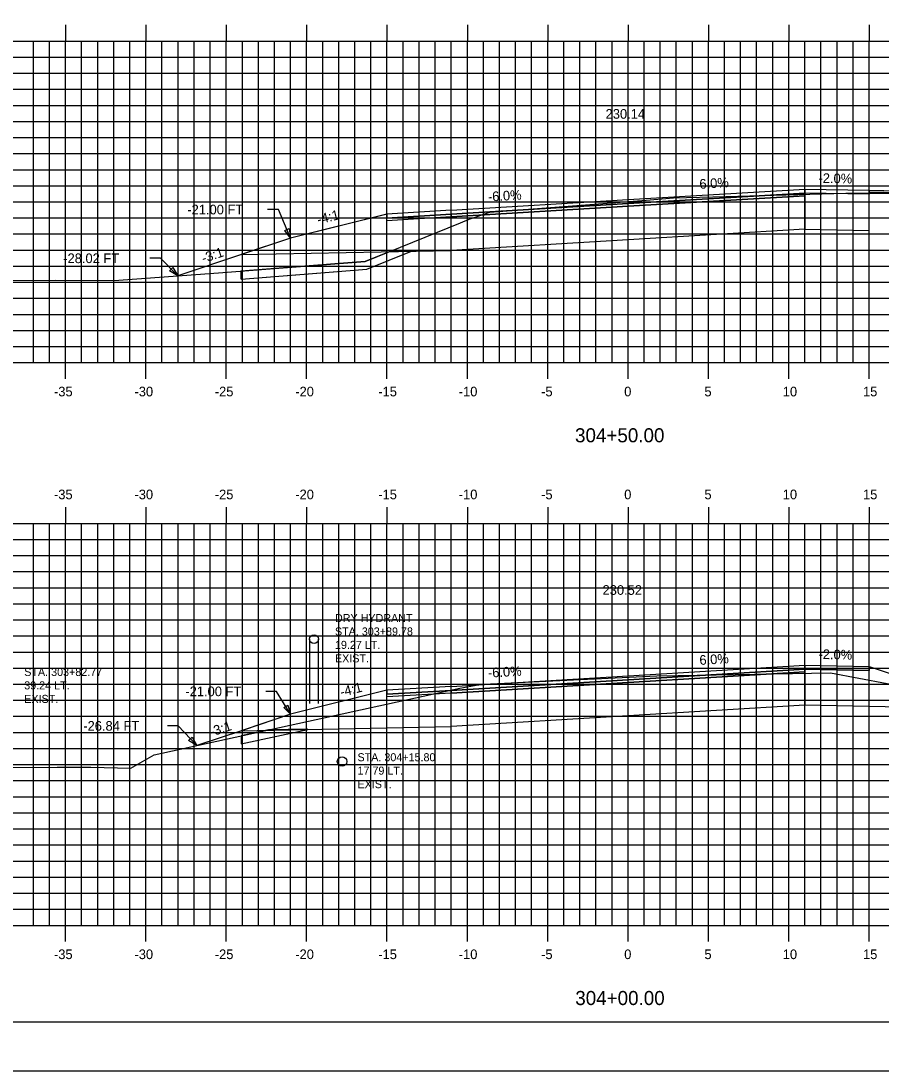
# Model space of a CAD drawing. Extents: x 1136989 to 1137159, y 608981 to 609091.
# Drawn here: x 1137034.4 to 1137087.9, y 608981.3 to 609046.6 of the extents above; entities that cross this region are included whole.
import ezdxf

# ---------------------------------------------------------------- set-up
doc = ezdxf.new("R2010")
doc.units = 0
for name, color, linetype in [('ANNOTATION', 7, 'Continuous'), ('BORDER', 7, 'Continuous'), ('D_Roadway_Centerline', 7, 'Continuous'), ('D_Roadway_Centerline_Text', 7, 'Continuous'), ('D_Roadway_Edge_Shoulder', 7, 'Continuous'), ('D_Roadway_Edge_TW', 7, 'Continuous'), ('D_Roadway_Pavement', 7, 'Continuous'), ('D_Roadway_SlopeLines', 7, 'Continuous'), ('D_Roadway_SubGrade', 7, 'Continuous'), ('D_Text_Monospaced', 7, 'Continuous'), ('D_Text_Standard', 7, 'Continuous'), ('H_V ANNOTATION', 7, 'Continuous'), ('MAJOR', 7, 'Continuous'), ('MINOR', 7, 'Continuous'), ('PLOT BOUNDARY', 7, 'Continuous'), ('S_Drainage_Invert', 7, 'Continuous'), ('S_Roadway_Centerline', 7, 'Continuous'), ('S_Traffic_Post_Conc', 7, 'Continuous'), ('SHADING', 7, 'Continuous')]:
    doc.layers.add(name, color=color, linetype=linetype)

msp = doc.modelspace()

# ---------------------------------------------------------------- linework, layer by layer
at = {"layer": 'BORDER'}
msp.add_lwpolyline([(1136997.14, 608984.335), (1137157.14, 608984.335), (1137157.14, 609089.335), (1136997.14, 609089.335)], close=True, dxfattribs=at)
at = {"layer": 'D_Roadway_Centerline'}
for points in [[(1137057.141, 609034.572), (1137051.141, 609033.073), (1137048.141, 609032.073), (1137044.117, 609030.731)], [(1137057.14, 609004.96), (1137051.14, 609003.46), (1137048.14, 609002.46), (1137045.302, 609001.514)]]:
    msp.add_lwpolyline(points, dxfattribs=at)
at = {"layer": 'D_Roadway_Edge_Shoulder'}
for points in [[(1137083.14, 609036.132), (1137087.14, 609036.052), (1137087.14, 609035.802), (1137083.14, 609035.882)], [(1137061.14, 609034.812), (1137057.14, 609034.572), (1137057.14, 609034.322), (1137061.14, 609034.562)], [(1137083.14, 609006.52), (1137087.14, 609006.44), (1137087.14, 609006.19), (1137083.14, 609006.27)], [(1137061.14, 609005.2), (1137057.14, 609004.96), (1137057.14, 609004.71), (1137061.14, 609004.95)]]:
    msp.add_lwpolyline(points, close=True, dxfattribs=at)
msp.add_lwpolyline([(1137087.14, 609036.052), (1137091.698, 609035.961), (1137091.695, 609035.836), (1137087.14, 609035.927)], dxfattribs=at)
at = {"layer": 'D_Roadway_Edge_TW'}
for points in [[(1137061.14, 609034.562), (1137061.14, 609034.812), (1137072.14, 609035.472), (1137083.14, 609036.132), (1137083.14, 609035.882), (1137072.14, 609035.222)], [(1137061.14, 609034.396), (1137057.14, 609034.158), (1137057.14, 609034.322), (1137061.14, 609034.562)], [(1137061.14, 609004.95), (1137061.14, 609005.2), (1137072.14, 609005.86), (1137083.14, 609006.52), (1137083.14, 609006.27), (1137072.14, 609005.61)], [(1137061.14, 609004.783), (1137057.14, 609004.543), (1137057.14, 609004.71), (1137061.14, 609004.95)]]:
    msp.add_lwpolyline(points, close=True, dxfattribs=at)
at = {"layer": 'D_Roadway_Pavement'}
for points in [[(1137061.14, 609034.396), (1137061.14, 609034.562), (1137072.14, 609035.222), (1137083.14, 609035.882), (1137083.14, 609035.716), (1137072.14, 609035.056)], [(1137061.14, 609004.783), (1137061.14, 609004.95), (1137072.14, 609005.61), (1137083.14, 609006.27), (1137083.14, 609006.103), (1137072.14, 609005.443)]]:
    msp.add_lwpolyline(points, close=True, dxfattribs=at)
at = {"layer": 'D_Roadway_SlopeLines'}
msp.add_line((1137048.076, 609030.525), (1137048.076, 609031.025), dxfattribs=at)
for points in [[(1137048.076, 609030.525), (1137055.894, 609031.14), (1137058.668, 609032.263)], [(1137048.075, 609002.119), (1137048.075, 609001.619), (1137052.206, 609002.521)]]:
    msp.add_lwpolyline(points, dxfattribs=at)
at = {"layer": 'D_Roadway_SubGrade'}
for points in [[(1137061.14, 609032.312), (1137061.14, 609034.396), (1137072.14, 609035.056), (1137083.14, 609035.716), (1137083.14, 609033.632), (1137072.14, 609032.972)], [(1137087.14, 609035.052), (1137087.14, 609036.052), (1137087.14, 609036.052), (1137087.14, 609035.802), (1137083.14, 609035.882), (1137083.14, 609035.716), (1137083.14, 609033.632), (1137087.14, 609033.552)], [(1137061.14, 609034.396), (1137061.14, 609034.562), (1137057.14, 609034.322), (1137057.14, 609034.572), (1137057.139, 609034.572), (1137051.141, 609033.073), (1137048.076, 609032.051), (1137061.14, 609032.312)], [(1137083.14, 609006.103), (1137083.14, 609006.27), (1137087.14, 609006.19), (1137087.14, 609006.44), (1137087.14, 609006.44), (1137095.119, 609003.78), (1137083.14, 609004.02)], [(1137061.14, 609002.7), (1137061.14, 609004.783), (1137072.14, 609005.443), (1137083.14, 609006.103), (1137083.14, 609004.02), (1137072.14, 609003.36)], [(1137061.14, 609004.783), (1137061.14, 609004.95), (1137057.14, 609004.71), (1137057.14, 609004.96), (1137057.139, 609004.96), (1137051.14, 609003.46), (1137048.075, 609002.438), (1137061.14, 609002.7)]]:
    msp.add_lwpolyline(points, close=True, dxfattribs=at)
at = {"layer": 'D_Text_Standard'}
for points in [[(1137051.141, 609033.073), (1137050.392, 609034.854), (1137049.712, 609034.854)], [(1137044.117, 609030.731), (1137043.057, 609031.823), (1137042.377, 609031.823)], [(1137051.14, 609003.46), (1137050.271, 609004.887), (1137049.591, 609004.887)], [(1137045.302, 609001.514), (1137044.154, 609002.742), (1137043.474, 609002.742)]]:
    msp.add_lwpolyline(points, dxfattribs=at)
for points in [[(1137051.141, 609033.073), (1137050.781, 609033.553), (1137051.049, 609033.666)], [(1137044.117, 609030.731), (1137043.607, 609031.048), (1137043.816, 609031.25)], [(1137051.14, 609003.46), (1137050.713, 609003.881), (1137050.961, 609004.033)], [(1137045.302, 609001.514), (1137044.799, 609001.84), (1137045.011, 609002.039)]]:
    msp.add_lwpolyline(points, close=True, dxfattribs=at)
at = {"layer": 'MAJOR'}
for p, q in [((1137037.14, 609046.337), (1137037.14, 609045.335)), ((1137042.14, 609046.337), (1137042.14, 609045.335)), ((1137047.14, 609046.337), (1137047.14, 609045.335)), ((1137052.14, 609046.337), (1137052.14, 609045.335)), ((1137057.14, 609046.337), (1137057.14, 609045.335)), ((1137062.14, 609046.337), (1137062.14, 609045.335)), ((1137067.14, 609046.337), (1137067.14, 609045.335)), ((1137072.14, 609046.337), (1137072.14, 609045.335)), ((1137077.14, 609046.337), (1137077.14, 609045.335)), ((1137082.14, 609046.337), (1137082.14, 609045.335)), ((1137087.14, 609046.337), (1137087.14, 609045.335)), ((1137002.14, 609045.335), (1137142.14, 609045.335)), ((1137002.14, 609045.335), (1137142.14, 609045.335)), ((1137037.14, 609025.335), (1137037.14, 609045.335)), ((1137042.14, 609025.335), (1137042.14, 609045.335)), ((1137047.14, 609025.335), (1137047.14, 609045.335)), ((1137052.14, 609025.335), (1137052.14, 609045.335)), ((1137057.14, 609025.335), (1137057.14, 609045.335)), ((1137062.14, 609025.335), (1137062.14, 609045.335)), ((1137067.14, 609025.335), (1137067.14, 609045.335)), ((1137072.14, 609025.335), (1137072.14, 609045.335)), ((1137077.14, 609025.335), (1137077.14, 609045.335)), ((1137082.14, 609025.335), (1137082.14, 609045.335)), ((1137087.14, 609025.335), (1137087.14, 609045.335)), ((1137002.14, 609040.335), (1137142.14, 609040.335)), ((1137002.14, 609035.335), (1137142.14, 609035.335)), ((1137002.14, 609030.335), (1137142.14, 609030.335)), ((1137002.14, 609025.335), (1137142.14, 609025.335)), ((1137002.14, 609025.335), (1137142.14, 609025.335)), ((1137037.14, 609024.333), (1137037.14, 609025.335)), ((1137042.14, 609024.333), (1137042.14, 609025.335)), ((1137047.14, 609024.333), (1137047.14, 609025.335)), ((1137052.14, 609024.333), (1137052.14, 609025.335)), ((1137057.14, 609024.333), (1137057.14, 609025.335)), ((1137062.14, 609024.333), (1137062.14, 609025.335)), ((1137067.14, 609024.333), (1137067.14, 609025.335)), ((1137072.14, 609024.333), (1137072.14, 609025.335)), ((1137077.14, 609024.333), (1137077.14, 609025.335)), ((1137082.14, 609024.333), (1137082.14, 609025.335)), ((1137087.14, 609024.333), (1137087.14, 609025.335)), ((1137037.14, 609016.337), (1137037.14, 609015.335)), ((1137042.14, 609016.337), (1137042.14, 609015.335)), ((1137047.14, 609016.337), (1137047.14, 609015.335)), ((1137052.14, 609016.337), (1137052.14, 609015.335)), ((1137057.14, 609016.337), (1137057.14, 609015.335)), ((1137062.14, 609016.337), (1137062.14, 609015.335)), ((1137067.14, 609016.337), (1137067.14, 609015.335)), ((1137072.14, 609016.337), (1137072.14, 609015.335)), ((1137077.14, 609016.337), (1137077.14, 609015.335)), ((1137082.14, 609016.337), (1137082.14, 609015.335)), ((1137087.14, 609016.337), (1137087.14, 609015.335)), ((1137002.14, 609015.335), (1137142.14, 609015.335)), ((1137002.14, 609015.335), (1137142.14, 609015.335)), ((1137037.14, 608990.335), (1137037.14, 609015.335)), ((1137042.14, 608990.335), (1137042.14, 609015.335)), ((1137047.14, 608990.335), (1137047.14, 609015.335)), ((1137052.14, 608990.335), (1137052.14, 609015.335)), ((1137057.14, 608990.335), (1137057.14, 609015.335)), ((1137062.14, 608990.335), (1137062.14, 609015.335)), ((1137067.14, 608990.335), (1137067.14, 609015.335)), ((1137072.14, 608990.335), (1137072.14, 609015.335)), ((1137077.14, 608990.335), (1137077.14, 609015.335)), ((1137082.14, 608990.335), (1137082.14, 609015.335)), ((1137087.14, 608990.335), (1137087.14, 609015.335)), ((1137002.14, 609010.335), (1137142.14, 609010.335)), ((1137002.14, 609005.335), (1137142.14, 609005.335)), ((1137002.14, 609000.335), (1137142.14, 609000.335)), ((1137002.14, 608995.335), (1137142.14, 608995.335)), ((1137002.14, 608990.335), (1137142.14, 608990.335)), ((1137002.14, 608990.335), (1137142.14, 608990.335)), ((1137037.14, 608989.333), (1137037.14, 608990.335)), ((1137042.14, 608989.333), (1137042.14, 608990.335)), ((1137047.14, 608989.333), (1137047.14, 608990.335)), ((1137052.14, 608989.333), (1137052.14, 608990.335)), ((1137057.14, 608989.333), (1137057.14, 608990.335)), ((1137062.14, 608989.333), (1137062.14, 608990.335)), ((1137067.14, 608989.333), (1137067.14, 608990.335)), ((1137072.14, 608989.333), (1137072.14, 608990.335)), ((1137077.14, 608989.333), (1137077.14, 608990.335)), ((1137082.14, 608989.333), (1137082.14, 608990.335)), ((1137087.14, 608989.333), (1137087.14, 608990.335))]:
    msp.add_line(p, q, dxfattribs=at)
at = {"layer": 'MINOR'}
for p, q in [((1137035.14, 609025.335), (1137035.14, 609045.335)), ((1137036.14, 609025.335), (1137036.14, 609045.335)), ((1137038.14, 609025.335), (1137038.14, 609045.335)), ((1137039.14, 609025.335), (1137039.14, 609045.335)), ((1137040.14, 609025.335), (1137040.14, 609045.335)), ((1137041.14, 609025.335), (1137041.14, 609045.335)), ((1137043.14, 609025.335), (1137043.14, 609045.335)), ((1137044.14, 609025.335), (1137044.14, 609045.335)), ((1137045.14, 609025.335), (1137045.14, 609045.335)), ((1137046.14, 609025.335), (1137046.14, 609045.335)), ((1137048.14, 609025.335), (1137048.14, 609045.335)), ((1137049.14, 609025.335), (1137049.14, 609045.335)), ((1137050.14, 609025.335), (1137050.14, 609045.335)), ((1137051.14, 609025.335), (1137051.14, 609045.335)), ((1137053.14, 609025.335), (1137053.14, 609045.335)), ((1137054.14, 609025.335), (1137054.14, 609045.335)), ((1137055.14, 609025.335), (1137055.14, 609045.335)), ((1137056.14, 609025.335), (1137056.14, 609045.335)), ((1137058.14, 609025.335), (1137058.14, 609045.335)), ((1137059.14, 609025.335), (1137059.14, 609045.335)), ((1137060.14, 609025.335), (1137060.14, 609045.335)), ((1137061.14, 609025.335), (1137061.14, 609045.335)), ((1137063.14, 609025.335), (1137063.14, 609045.335)), ((1137064.14, 609025.335), (1137064.14, 609045.335)), ((1137065.14, 609025.335), (1137065.14, 609045.335)), ((1137066.14, 609025.335), (1137066.14, 609045.335)), ((1137068.14, 609025.335), (1137068.14, 609045.335)), ((1137069.14, 609025.335), (1137069.14, 609045.335)), ((1137070.14, 609025.335), (1137070.14, 609045.335)), ((1137071.14, 609025.335), (1137071.14, 609045.335)), ((1137073.14, 609025.335), (1137073.14, 609045.335)), ((1137074.14, 609025.335), (1137074.14, 609045.335)), ((1137075.14, 609025.335), (1137075.14, 609045.335)), ((1137076.14, 609025.335), (1137076.14, 609045.335)), ((1137078.14, 609025.335), (1137078.14, 609045.335)), ((1137079.14, 609025.335), (1137079.14, 609045.335)), ((1137080.14, 609025.335), (1137080.14, 609045.335)), ((1137081.14, 609025.335), (1137081.14, 609045.335)), ((1137083.14, 609025.335), (1137083.14, 609045.335)), ((1137084.14, 609025.335), (1137084.14, 609045.335)), ((1137085.14, 609025.335), (1137085.14, 609045.335)), ((1137086.14, 609025.335), (1137086.14, 609045.335)), ((1137002.14, 609044.335), (1137142.14, 609044.335)), ((1137002.14, 609043.335), (1137142.14, 609043.335)), ((1137002.14, 609042.335), (1137142.14, 609042.335)), ((1137002.14, 609041.335), (1137142.14, 609041.335)), ((1137002.14, 609039.335), (1137142.14, 609039.335)), ((1137002.14, 609038.335), (1137142.14, 609038.335)), ((1137002.14, 609037.335), (1137142.14, 609037.335)), ((1137002.14, 609036.335), (1137142.14, 609036.335)), ((1137002.14, 609034.335), (1137142.14, 609034.335)), ((1137002.14, 609033.335), (1137142.14, 609033.335)), ((1137002.14, 609032.335), (1137142.14, 609032.335)), ((1137002.14, 609031.335), (1137142.14, 609031.335)), ((1137002.14, 609029.335), (1137142.14, 609029.335)), ((1137002.14, 609028.335), (1137142.14, 609028.335)), ((1137002.14, 609027.335), (1137142.14, 609027.335)), ((1137002.14, 609026.335), (1137142.14, 609026.335)), ((1137035.14, 608990.335), (1137035.14, 609015.335)), ((1137036.14, 608990.335), (1137036.14, 609015.335)), ((1137038.14, 608990.335), (1137038.14, 609015.335)), ((1137039.14, 608990.335), (1137039.14, 609015.335)), ((1137040.14, 608990.335), (1137040.14, 609015.335)), ((1137041.14, 608990.335), (1137041.14, 609015.335)), ((1137043.14, 608990.335), (1137043.14, 609015.335)), ((1137044.14, 608990.335), (1137044.14, 609015.335)), ((1137045.14, 608990.335), (1137045.14, 609015.335)), ((1137046.14, 608990.335), (1137046.14, 609015.335)), ((1137048.14, 608990.335), (1137048.14, 609015.335)), ((1137049.14, 608990.335), (1137049.14, 609015.335)), ((1137050.14, 608990.335), (1137050.14, 609015.335)), ((1137051.14, 608990.335), (1137051.14, 609015.335)), ((1137053.14, 608990.335), (1137053.14, 609015.335)), ((1137054.14, 608990.335), (1137054.14, 609015.335)), ((1137055.14, 608990.335), (1137055.14, 609015.335)), ((1137056.14, 608990.335), (1137056.14, 609015.335)), ((1137058.14, 608990.335), (1137058.14, 609015.335)), ((1137059.14, 608990.335), (1137059.14, 609015.335)), ((1137060.14, 608990.335), (1137060.14, 609015.335)), ((1137061.14, 608990.335), (1137061.14, 609015.335)), ((1137063.14, 608990.335), (1137063.14, 609015.335)), ((1137064.14, 608990.335), (1137064.14, 609015.335)), ((1137065.14, 608990.335), (1137065.14, 609015.335)), ((1137066.14, 608990.335), (1137066.14, 609015.335)), ((1137068.14, 608990.335), (1137068.14, 609015.335)), ((1137069.14, 608990.335), (1137069.14, 609015.335)), ((1137070.14, 608990.335), (1137070.14, 609015.335)), ((1137071.14, 608990.335), (1137071.14, 609015.335)), ((1137073.14, 608990.335), (1137073.14, 609015.335)), ((1137074.14, 608990.335), (1137074.14, 609015.335)), ((1137075.14, 608990.335), (1137075.14, 609015.335)), ((1137076.14, 608990.335), (1137076.14, 609015.335)), ((1137078.14, 608990.335), (1137078.14, 609015.335)), ((1137079.14, 608990.335), (1137079.14, 609015.335)), ((1137080.14, 608990.335), (1137080.14, 609015.335)), ((1137081.14, 608990.335), (1137081.14, 609015.335)), ((1137083.14, 608990.335), (1137083.14, 609015.335)), ((1137084.14, 608990.335), (1137084.14, 609015.335)), ((1137085.14, 608990.335), (1137085.14, 609015.335)), ((1137086.14, 608990.335), (1137086.14, 609015.335)), ((1137002.14, 609014.335), (1137142.14, 609014.335)), ((1137002.14, 609013.335), (1137142.14, 609013.335)), ((1137002.14, 609012.335), (1137142.14, 609012.335)), ((1137002.14, 609011.335), (1137142.14, 609011.335)), ((1137002.14, 609009.335), (1137142.14, 609009.335)), ((1137002.14, 609008.335), (1137142.14, 609008.335)), ((1137002.14, 609007.335), (1137142.14, 609007.335)), ((1137002.14, 609006.335), (1137142.14, 609006.335)), ((1137002.14, 609004.335), (1137142.14, 609004.335)), ((1137002.14, 609003.335), (1137142.14, 609003.335)), ((1137002.14, 609002.335), (1137142.14, 609002.335)), ((1137002.14, 609001.335), (1137142.14, 609001.335)), ((1137002.14, 608999.335), (1137142.14, 608999.335)), ((1137002.14, 608998.335), (1137142.14, 608998.335)), ((1137002.14, 608997.335), (1137142.14, 608997.335)), ((1137002.14, 608996.335), (1137142.14, 608996.335)), ((1137002.14, 608994.335), (1137142.14, 608994.335)), ((1137002.14, 608993.335), (1137142.14, 608993.335)), ((1137002.14, 608992.335), (1137142.14, 608992.335)), ((1137002.14, 608991.335), (1137142.14, 608991.335))]:
    msp.add_line(p, q, dxfattribs=at)
at = {"layer": 'PLOT BOUNDARY'}
msp.add_lwpolyline([(1136989.047, 608981.276), (1137159.047, 608981.276), (1137159.047, 609091.276), (1136989.047, 609091.276)], close=True, dxfattribs=at)
at = {"layer": 'S_Drainage_Invert'}
msp.add_circle((1137054.348, 609000.526), 0.3, dxfattribs=at)
at = {"layer": 'S_Roadway_Centerline'}
for points in [[(1137002.14, 609030.462), (1137003.399, 609030.449), (1137006.342, 609030.492), (1137015.185, 609030.419), (1137018.549, 609030.394), (1137019.238, 609030.446), (1137022.99, 609030.389), (1137036.519, 609030.456), (1137040.174, 609030.448), (1137046.657, 609030.914), (1137055.778, 609031.631), (1137061.718, 609034.034), (1137062.247, 609034.265), (1137063.541, 609034.695), (1137073.261, 609035.448), (1137074.968, 609035.579), (1137078.218, 609035.668), (1137085.691, 609035.878), (1137089.945, 609035.87)], [(1137002.14, 609000.098), (1137009.532, 609000.178), (1137012.739, 609000.098), (1137016.466, 609000.152), (1137036.626, 609000.169), (1137038.714, 609000.163), (1137041.2, 609000.115), (1137042.648, 609000.935), (1137061.665, 609005.086), (1137063.035, 609005.338), (1137063.585, 609005.359), (1137073.925, 609005.86), (1137075.247, 609005.88), (1137084.732, 609006.033), (1137090.016, 609005.053), (1137090.597, 609004.926), (1137092.675, 609004.125), (1137094.237, 609003.522), (1137106.232, 609002.947), (1137113.452, 609002.818), (1137121.89, 609002.73), (1137136.879, 609002.44), (1137141.584, 609002.392), (1137142.14, 609002.4)]]:
    msp.add_lwpolyline(points, dxfattribs=at)
at = {"layer": 'S_Traffic_Post_Conc'}
for p, q in [((1137052.329, 609004.134), (1137052.329, 609008.134)), ((1137052.87, 609004.134), (1137052.87, 609008.134))]:
    msp.add_line(p, q, dxfattribs=at)
msp.add_circle((1137052.599, 609008.134), 0.271, dxfattribs=at)
at = {"layer": 'SHADING'}
for p, q in [((1137049.774, 609002.49), (1137048.075, 609002.119)), ((1137052.206, 609002.535), (1137049.774, 609002.49))]:
    msp.add_line(p, q, dxfattribs=at)
msp.add_lwpolyline([(1137048.076, 609031.025), (1137048.076, 609030.525), (1137051.985, 609030.833), (1137055.894, 609031.14), (1137058.668, 609032.263), (1137057.27, 609032.235), (1137055.778, 609031.631), (1137051.218, 609031.272)], close=True, dxfattribs=at)
for points in [[(1137048.075, 609002.119), (1137048.075, 609001.619), (1137052.206, 609002.521)], [(1137052.206, 609002.521), (1137052.206, 609002.535)]]:
    msp.add_lwpolyline(points, dxfattribs=at)

# ---------------------------------------------------------------- texts
at = {"layer": 'ANNOTATION'}
for s, rotation, p in [('6.0%', 3.43363, (1137076.597, 609036.142)), ('-2.0%', 358.85424, (1137083.983, 609036.516)), ('-6.0%', 3.43363, (1137063.437, 609035.352)), ('-4:1', 14.03624, (1137052.872, 609033.927)), ('-3:1', 18.43483, (1137045.716, 609031.52)), ('-2.0%', 358.85424, (1137083.983, 609006.903)), ('6.0%', 3.43363, (1137076.597, 609006.529)), ('-6.0%', 3.43363, (1137063.437, 609005.739)), ('-4:1', 14.03624, (1137054.302, 609004.545)), ('-3:1', 18.43483, (1137046.211, 609002.062))]:
    msp.add_text(s, height=0.6, rotation=rotation, dxfattribs=at).set_placement(p)
at = {"layer": 'D_Roadway_Centerline'}
for s, p in [('C', (1137072.135, 609035.472)), ('L', (1137072.14, 609035.465)), ('C', (1137072.135, 609005.86)), ('L', (1137072.14, 609005.852))]:
    msp.add_text(s, height=0.0146, dxfattribs=at).set_placement(p)
at = {"layer": 'D_Roadway_Centerline_Text'}
for s, p in [('230.14', (1137070.743, 609040.504)), ('230.52', (1137070.553, 609010.892))]:
    msp.add_text(s, height=0.6, dxfattribs=at).set_placement(p)
at = {"layer": 'D_Text_Monospaced'}
for s, height, p in [('DRY HYDRANT', 0.49998, (1137053.902, 609009.198)), ('STA. 303+89.78', 0.49998, (1137053.902, 609008.364)), ('19.27 LT.', 0.5, (1137053.902, 609007.53)), ('EXIST. ', 0.5, (1137053.902, 609006.69)), ('STA. 303+82.77', 0.49998, (1137034.569, 609005.844)), ('39.24 LT.', 0.5, (1137034.569, 609005.01)), ('EXIST. ', 0.5, (1137034.569, 609004.17)), ('STA. 304+15.80', 0.49998, (1137055.304, 609000.541)), ('17.79 LT.', 0.5, (1137055.304, 608999.707)), ('EXIST. ', 0.5, (1137055.304, 608998.867))]:
    msp.add_text(s, height=height, dxfattribs=at).set_placement(p)
at = {"layer": 'D_Text_Standard'}
for s, p in [('-21.00 FT', (1137044.717, 609034.554)), ('-28.02 FT', (1137036.997, 609031.523)), ('-21.00 FT', (1137044.596, 609004.587)), ('-26.84 FT', (1137038.244, 609002.442))]:
    msp.add_text(s, height=0.6, dxfattribs=at).set_placement(p)
at = {"layer": 'H_V ANNOTATION'}
for s, height, p in [('-35', 0.6, (1137036.42, 609023.235)), ('-30', 0.6, (1137041.428, 609023.235)), ('-25', 0.6, (1137046.425, 609023.235)), ('-20', 0.6, (1137051.433, 609023.235)), ('-15', 0.6, (1137056.597, 609023.235)), ('-10', 0.6, (1137061.605, 609023.235)), ('-5', 0.6, (1137066.73, 609023.235)), ('0', 0.6, (1137071.899, 609023.235)), ('5', 0.6, (1137076.891, 609023.235)), ('10', 0.6, (1137081.765, 609023.235)), ('15', 0.6, (1137086.757, 609023.235)), ('304+50.00', 0.875, (1137068.839, 609020.378)), ('-35', 0.6, (1137036.42, 609016.835)), ('-30', 0.6, (1137041.428, 609016.835)), ('-25', 0.6, (1137046.425, 609016.835)), ('-20', 0.6, (1137051.433, 609016.835)), ('-15', 0.6, (1137056.597, 609016.835)), ('-10', 0.6, (1137061.605, 609016.835)), ('-5', 0.6, (1137066.73, 609016.835)), ('0', 0.6, (1137071.899, 609016.835)), ('5', 0.6, (1137076.891, 609016.835)), ('10', 0.6, (1137081.765, 609016.835)), ('15', 0.6, (1137086.757, 609016.835)), ('-35', 0.6, (1137036.42, 608988.235)), ('-30', 0.6, (1137041.428, 608988.235)), ('-25', 0.6, (1137046.425, 608988.235)), ('-20', 0.6, (1137051.433, 608988.235)), ('-15', 0.6, (1137056.597, 608988.235)), ('-10', 0.6, (1137061.605, 608988.235)), ('-5', 0.6, (1137066.73, 608988.235)), ('0', 0.6, (1137071.899, 608988.235)), ('5', 0.6, (1137076.891, 608988.235)), ('10', 0.6, (1137081.765, 608988.235)), ('15', 0.6, (1137086.757, 608988.235)), ('304+00.00', 0.875, (1137068.855, 608985.378))]:
    msp.add_text(s, height=height, dxfattribs=at).set_placement(p)
at = {"layer": 'S_Roadway_Centerline'}
for s, p in [('C', (1137074.963, 609035.579)), ('L', (1137074.968, 609035.572)), ('C', (1137073.92, 609005.86)), ('L', (1137073.925, 609005.853))]:
    msp.add_text(s, height=0.0146, dxfattribs=at).set_placement(p)

doc.saveas('drawing.dxf')
